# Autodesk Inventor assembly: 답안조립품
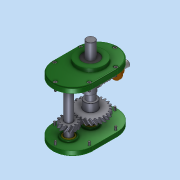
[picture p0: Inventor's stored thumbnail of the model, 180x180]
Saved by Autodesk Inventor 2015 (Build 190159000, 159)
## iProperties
Created: 2018-07
Part Number: 답안조립품
Document SubType Name: Assembly
Designer: SCD-A03
Author: SCD-A03
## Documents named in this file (14)
- C:\Users\SCD-A03\Desktop\380707V1010\답안조립품.iam
- C:\Users\SCD-A03\Desktop\380707V1010\본체.ipt
- C:\Users\SCD-A03\Desktop\380707V1010\앞커버.ipt
- C:\Users\SCD-A03\Desktop\380707V1010\뒤커버.ipt
- C:\Users\SCD-A03\Desktop\380707V1010\베어링 608.ipt
- C:\Users\SCD-A03\Desktop\380707V1010\베어링 6003.ipt
- C:\Users\SCD-A03\Desktop\380707V1010\오일 실 8 22 7.ipt
- C:\Users\SCD-A03\Desktop\380707V1010\오일 실 17 32 8.ipt
- C:\Users\SCD-A03\Desktop\380707V1010\볼트 M4.ipt
- C:\Users\SCD-A03\Desktop\380707V1010\메인축.ipt
- C:\Users\SCD-A03\Desktop\380707V1010\서브축.ipt
- C:\Users\SCD-A03\Desktop\380707V1010\부시.ipt
- C:\Users\SCD-A03\Desktop\380707V1010\슬라이더.ipt
- C:\Users\SCD-A03\Desktop\380707V1010\가변스프링.ipt
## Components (1 placed, 1 different names)
1. 가변스프링:1
